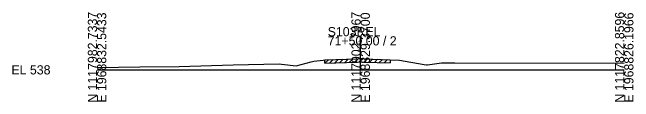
# Model space of a CAD drawing. Extents: x -26 to 163, y -10 to 24518.
# Drawn here: x -25.7 to 162.8, y 19990.3 to 20017.5 of the extents above; entities that cross this region are included whole.
import ezdxf

# ---------------------------------------------------------------- set-up
doc = ezdxf.new("R2010")
doc.units = 0
for name, color, linetype in [('RD_GPK_XS_Cell', 7, 'Continuous'), ('RD_XS_ExGround', 7, 'Continuous'), ('RD_XS_ExPaveRet', 7, 'Continuous'), ('RD_XS_TX_Elev_EX', 7, 'Continuous')]:
    doc.layers.add(name, color=color, linetype=linetype)

msp = doc.modelspace()

# ---------------------------------------------------------------- linework, layer by layer
at = {"layer": 'RD_GPK_XS_Cell'}
for p, q in [((80, 20000), (80, 20010.24)), ((0, 20000), (80, 20000)), ((80, 20000), (160, 20000))]:
    msp.add_line(p, q, dxfattribs=at)
at = {"layer": 'RD_XS_ExGround'}
msp.add_lwpolyline([(0, 20000.67), (12.96, 20000.89), (24.91, 20001.02), (41.3, 20001.48), (55.24, 20001.88), (56.02, 20001.77), (60.41, 20001.23), (65, 20002.41), (65.75, 20002.6), (68.67, 20002.98), (69.16, 20003.04), (79.02, 20003.38), (80.14, 20003.41), (81.04, 20003.38), (89.01, 20003.09), (91.77, 20002.96), (99.26, 20001.64), (99.96, 20001.52), (100.32, 20001.57), (104.53, 20002.17), (105.63, 20002.12), (108.59, 20002.18), (160, 20002.01)], dxfattribs=at)
at = {"layer": 'RD_XS_ExPaveRet'}
for p, q in [((76.66, 20002.3), (77.7, 20003.33)), ((78.16, 20002.35), (79.2, 20003.38)), ((79.66, 20002.4), (80.66, 20003.4)), ((81.16, 20002.38), (82.13, 20003.34)), ((69.16, 20002.04), (70.2, 20003.08)), ((69.16, 20002.04), (69.16, 20003.04)), ((69.16, 20002.04), (79.02, 20002.38)), ((70.66, 20002.09), (71.7, 20003.13)), ((72.16, 20002.15), (73.2, 20003.18)), ((73.66, 20002.2), (74.7, 20003.23)), ((75.16, 20002.25), (76.2, 20003.28)), ((79.02, 20002.38), (80.14, 20002.41)), ((80.14, 20002.41), (81.04, 20002.38)), ((81.04, 20002.38), (89.01, 20002.09)), ((82.66, 20002.32), (83.63, 20003.29)), ((84.16, 20002.27), (85.13, 20003.23)), ((85.66, 20002.21), (86.63, 20003.18)), ((87.16, 20002.16), (88.13, 20003.12)), ((89.01, 20003.09), (89.01, 20002.09))]:
    msp.add_line(p, q, dxfattribs=at)

# ---------------------------------------------------------------- texts
at = {"layer": 'RD_GPK_XS_Cell'}
for s, p in [('N 1117982.7337', (0, 19990)), ('E 1968832.5433', (2.8, 19990)), ('N 1117902.7967', (80, 19990)), ('E 1968829.3700', (82.8, 19990)), ('N 1117822.8596', (160, 19990)), ('E 1968826.1966', (162.8, 19990))]:
    msp.add_text(s, height=2.8, rotation=90, dxfattribs=at).set_placement(p)
for s, p in [('S103REL', (70, 20010.24)), ('71+50.00 / 2', (70, 20007.44)), ('EL 538', (-26, 19998.6))]:
    msp.add_text(s, height=2.8, dxfattribs=at).set_placement(p)
at = {"layer": 'RD_XS_TX_Elev_EX'}
msp.add_text('541.41', height=0.8, rotation=90, dxfattribs=at).set_placement((79.9, 20005.41))

doc.saveas('drawing.dxf')
